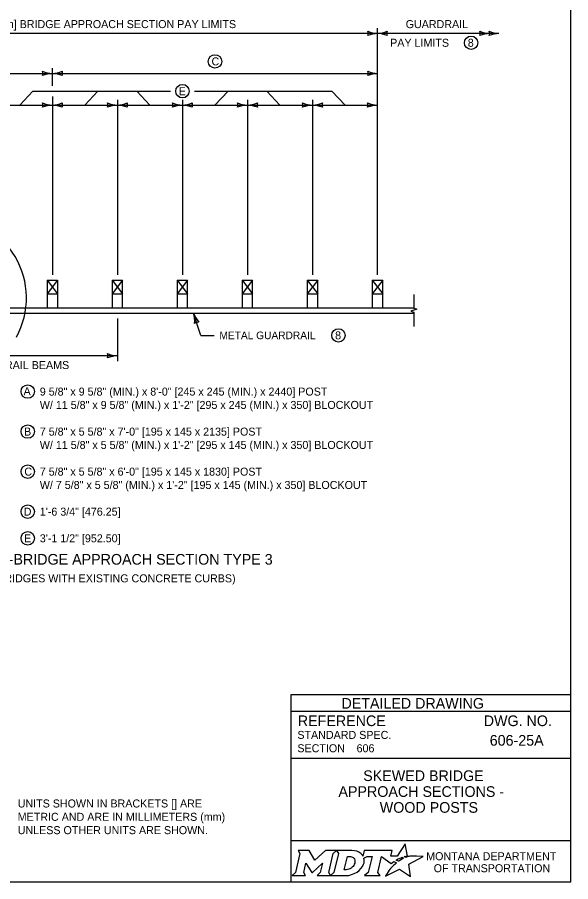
# Model space of a CAD drawing. Extents: x 49991.4 to 50021, y 49987.6 to 50011.4.
# Drawn here: x 50004.46 to 50008.61, y 50000.06 to 50006.54 of the extents above; entities that cross this region are included whole.
import ezdxf

# ---------------------------------------------------------------- set-up
doc = ezdxf.new("R2010")
doc.units = 0
for name, color, linetype in [('Level 1', 7, 'Continuous'), ('Level 2', 7, 'Continuous'), ('Level 3', 7, 'Continuous'), ('Level 4', 7, 'Continuous'), ('Level 6', 7, 'Continuous')]:
    doc.layers.add(name, color=color, linetype=linetype)

msp = doc.modelspace()

# ---------------------------------------------------------------- linework, layer by layer
at = {"layer": 'Level 1'}
for p, q in [((50004.6885, 50004.5728), (50004.7665, 50004.5728)), ((50004.7665, 50004.5728), (50004.6885, 50004.4688)), ((50004.6885, 50004.5728), (50004.7665, 50004.4688)), ((50004.6885, 50004.5728), (50004.6885, 50004.3647)), ((50004.7665, 50004.5728), (50004.7665, 50004.3647)), ((50005.1762, 50004.5728), (50005.2542, 50004.5728)), ((50005.2542, 50004.5728), (50005.1762, 50004.4688)), ((50005.1762, 50004.5728), (50005.2542, 50004.4688)), ((50005.1762, 50004.5728), (50005.1762, 50004.3647)), ((50005.2542, 50004.3647), (50005.2542, 50004.5728)), ((50005.6639, 50004.5728), (50005.7419, 50004.5728)), ((50005.7419, 50004.5728), (50005.6639, 50004.4688)), ((50005.6639, 50004.5728), (50005.7419, 50004.4688)), ((50005.6639, 50004.5728), (50005.6639, 50004.3647)), ((50005.7419, 50004.3647), (50005.7419, 50004.5728)), ((50006.1515, 50004.5728), (50006.2296, 50004.5728)), ((50006.2296, 50004.5728), (50006.1515, 50004.4688)), ((50006.1515, 50004.5728), (50006.2296, 50004.4688)), ((50006.1515, 50004.5728), (50006.1515, 50004.3647)), ((50006.2296, 50004.3647), (50006.2296, 50004.5728)), ((50006.6392, 50004.5728), (50006.7173, 50004.5728)), ((50006.7173, 50004.5728), (50006.6392, 50004.4688)), ((50006.6392, 50004.5728), (50006.7173, 50004.4688)), ((50006.6392, 50004.5728), (50006.6392, 50004.3647)), ((50006.7173, 50004.3647), (50006.7173, 50004.5728)), ((50007.1269, 50004.5728), (50007.205, 50004.5728)), ((50007.205, 50004.5728), (50007.1269, 50004.4688)), ((50007.1269, 50004.5728), (50007.205, 50004.4688)), ((50007.1269, 50004.5728), (50007.1269, 50004.3647)), ((50007.205, 50004.3647), (50007.205, 50004.5728)), ((50004.6885, 50004.4688), (50004.7665, 50004.4688)), ((50005.1762, 50004.4688), (50005.2542, 50004.4688)), ((50005.6639, 50004.4688), (50005.7419, 50004.4688)), ((50006.1515, 50004.4688), (50006.2296, 50004.4688)), ((50006.6392, 50004.4688), (50006.7173, 50004.4688)), ((50007.1269, 50004.4688), (50007.205, 50004.4688)), ((50001.87, 50004.3647), (50007.4379, 50004.3647)), ((50001.87, 50004.3256), (50007.4379, 50004.3256))]:
    msp.add_line(p, q, dxfattribs=at)
msp.add_lwpolyline([(50008.6146, 50011.2628), (50000.3356, 50011.2628), (50000.3356, 50000.0624), (50008.6146, 50000.0624)], close=True, dxfattribs=at)
at = {"layer": 'Level 2'}
for p, q in [((50008.6146, 50001.4624), (50006.5146, 50001.4624)), ((50006.5146, 50001.4624), (50006.5146, 50000.0624)), ((50008.6146, 50001.3374), (50006.5146, 50001.3374)), ((50007.0089, 50001.0629), (50007.0089, 50001.0629)), ((50008.2507, 50001.1223), (50008.2507, 50001.1223)), ((50008.6146, 50000.9874), (50006.5146, 50000.9874)), ((50007.5646, 50000.7383), (50007.5646, 50000.7383)), ((50008.6146, 50000.3693), (50006.5146, 50000.3693))]:
    msp.add_line(p, q, dxfattribs=at)
for points in [[(50006.5701, 50000.2974), (50006.5842, 50000.274), (50006.5507, 50000.1307), (50006.525, 50000.1082), (50006.6266, 50000.1082), (50006.6131, 50000.131), (50006.6293, 50000.2011), (50006.673, 50000.1321), (50006.6783, 50000.1321), (50006.7534, 50000.2016), (50006.737, 50000.1305), (50006.7123, 50000.1085), (50006.8139, 50000.1085), (50006.8001, 50000.1318), (50006.8333, 50000.2742)], [(50006.8333, 50000.2742), (50006.8586, 50000.2974), (50006.7762, 50000.2974), (50006.6966, 50000.2244), (50006.6521, 50000.2971), (50006.5701, 50000.2974)], [(50006.9722, 50000.2974), (50006.8586, 50000.2974), (50006.8733, 50000.2745), (50006.8394, 50000.1307), (50006.8139, 50000.1085), (50006.9245, 50000.1085)], [(50007.3771, 50000.2447), (50007.3668, 50000.2503), (50007.3784, 50000.2531), (50007.39, 50000.2551), (50007.3726, 50000.3452), (50007.3131, 50000.2539), (50007.2658, 50000.2532), (50007.2761, 50000.2973), (50007.0669, 50000.2974), (50007.0568, 50000.2549), (50007.051, 50000.2632)], [(50006.9962, 50000.2107), (50006.995, 50000.2026), (50006.9918, 50000.1933), (50006.9876, 50000.1851), (50006.982, 50000.1776), (50006.9755, 50000.1707), (50006.9676, 50000.1644), (50006.9593, 50000.1597), (50006.9502, 50000.1558), (50006.9411, 50000.1535), (50006.9319, 50000.1526), (50006.916, 50000.1526), (50006.9396, 50000.2526), (50006.9556, 50000.2526), (50006.9632, 50000.252), (50006.9708, 50000.2501), (50006.9774, 50000.2471), (50006.9835, 50000.2429), (50006.9883, 50000.2379), (50006.992, 50000.2319), (50006.9947, 50000.2257), (50006.9963, 50000.2183), (50006.9963, 50000.2153), (50006.9962, 50000.2107)], [(50007.0636, 50000.2383), (50007.0882, 50000.2514), (50007.1251, 50000.2514), (50007.0965, 50000.1309), (50007.069, 50000.1082), (50007.1852, 50000.1082), (50007.1682, 50000.1311), (50007.1964, 50000.2513), (50007.2677, 50000.1996), (50007.2888, 50000.2147), (50007.3085, 50000.2038)], [(50007.2527, 50000.1479), (50007.2374, 50000.1235), (50007.2327, 50000.116), (50007.2269, 50000.1074), (50007.2246, 50000.1031), (50007.3299, 50000.1562), (50007.4138, 50000.1011), (50007.4007, 50000.1938), (50007.5076, 50000.2522), (50007.4583, 50000.253), (50007.4282, 50000.2534), (50007.4074, 50000.2537), (50007.4006, 50000.2522), (50007.3957, 50000.251), (50007.3873, 50000.2487), (50007.3771, 50000.2447)], [(50007.3267, 50000.2171), (50007.3243, 50000.2154), (50007.306, 50000.225), (50007.3163, 50000.2307), (50007.3204, 50000.2329), (50007.329, 50000.2369), (50007.3347, 50000.2395), (50007.3426, 50000.2425), (50007.3499, 50000.2452), (50007.3617, 50000.2378), (50007.3577, 50000.2357), (50007.3531, 50000.2332), (50007.3489, 50000.231), (50007.3439, 50000.2281), (50007.342, 50000.227), (50007.3393, 50000.2254), (50007.3368, 50000.224), (50007.3345, 50000.2224), (50007.3319, 50000.2206), (50007.3292, 50000.2188), (50007.3267, 50000.2171)], [(50007.2666, 50000.164), (50007.2666, 50000.164)], [(50006.9702, 50000.1158), (50006.9786, 50000.1184), (50006.9916, 50000.1238), (50007.012, 50000.1348)]]:
    msp.add_lwpolyline(points, dxfattribs=at)
for centre, radius in [((50007.8676, 50006.3522), 0.05), ((50005.9468, 50006.2126), 0.0504), ((50005.7029, 50005.9893), 0.0504), ((50006.8729, 50004.1585), 0.05), ((50004.543, 50003.737), 0.0504), ((50004.543, 50003.437), 0.0504), ((50004.543, 50003.137), 0.0504), ((50004.543, 50002.837), 0.0504), ((50004.543, 50002.637), 0.0504)]:
    msp.add_circle(centre, radius, dxfattribs=at)
for centre, radius, start, end in [((50006.9953, 50000.219), 0.0709, 339.53292, 15.85821), ((50006.9513, 50000.2363), 0.1183, 300.91025, 339.13831)]:
    msp.add_arc(centre, radius, start, end, dxfattribs=at)
for centre, major_axis, ratio, start_param, end_param in [((50006.9701, 50000.25), (0.0834, -0.0037), 0.568097, 0.61298, 1.570796), ((50007.0257, 50000.2573), (0.0361, -0.0295), 0.469099, 1.225588, 1.570796), ((50007.2597, 50000.1559), (-0.00694, -0.00806), 0.008222, 0, 3.137361), ((50007.2764, 50000.1742), (-0.0098, -0.0102), 0.016458, 3.141593, 6.279097), ((50007.2974, 50000.1941), (-0.0112, -0.0097), 0.021651, 3.157348, 6.283185), ((50006.9248, 50000.2568), (0, 0.1484), 0.987302, 3.139398, 3.456847)]:
    msp.add_ellipse(centre, major_axis=major_axis, ratio=ratio, start_param=start_param, end_param=end_param, dxfattribs=at)
at = {"layer": 'Level 3'}
for p, q in [((50007.1658, 50004.6128), (50007.1658, 50006.4622)), ((50007.1658, 50006.4222), (50003.2643, 50006.4222)), ((50008.0755, 50006.4222), (50007.1658, 50006.4222)), ((50003.7521, 50006.1222), (50004.7275, 50006.1222)), ((50004.7275, 50006.0294), (50004.7275, 50006.1622)), ((50004.7275, 50006.1222), (50007.1658, 50006.1222)), ((50004.5818, 50005.9894), (50004.4836, 50005.8849)), ((50004.5818, 50005.9894), (50005.6125, 50005.9894)), ((50005.0696, 50005.9894), (50004.9713, 50005.8849)), ((50005.3607, 50005.9894), (50005.459, 50005.8849)), ((50005.7933, 50005.9894), (50006.8238, 50005.9894)), ((50006.0449, 50005.9894), (50005.9467, 50005.8849)), ((50006.3361, 50005.9894), (50006.4344, 50005.8849)), ((50006.8238, 50005.9894), (50006.9221, 50005.8849)), ((50004.7275, 50005.9494), (50004.7275, 50004.6128)), ((50005.2152, 50005.9249), (50005.2152, 50004.6128)), ((50005.7029, 50005.9249), (50005.7029, 50004.6128)), ((50006.1906, 50005.9249), (50006.1906, 50004.6128)), ((50006.6783, 50005.9249), (50006.6783, 50004.6128)), ((50004.2398, 50005.8849), (50004.7275, 50005.8849)), ((50004.7275, 50005.8849), (50005.2152, 50005.8849)), ((50005.2152, 50005.8849), (50005.7029, 50005.8849)), ((50005.7029, 50005.8849), (50006.1906, 50005.8849)), ((50006.1906, 50005.8849), (50006.6783, 50005.8849)), ((50006.6783, 50005.8849), (50007.1658, 50005.8849)), ((50005.8409, 50004.1586), (50005.7866, 50004.3256)), ((50005.2152, 50004.2856), (50005.2152, 50003.966)), ((50005.8409, 50004.1586), (50005.9407, 50004.1586)), ((50005.2152, 50004.006), (50003.2644, 50004.006))]:
    msp.add_line(p, q, dxfattribs=at)
for centre, radius, start, end in [((50007.1745, 50006.6332), 0.2113, 247.45601, 267.63952), ((50007.044, 50006.4222), 0.0521, 342.13882, 17.86118), ((50007.1549, 50006.6433), 0.2214, 272.82731, 292.07716), ((50007.2877, 50006.4222), 0.0521, 162.13882, 197.86118), ((50008.0144, 50006.6332), 0.2113, 247.45601, 267.63952), ((50007.8839, 50006.4222), 0.0521, 342.13882, 17.86118), ((50008.0842, 50006.6332), 0.2113, 247.45601, 267.63952), ((50007.9537, 50006.4222), 0.0521, 342.13882, 17.86118), ((50007.1768, 50006.201), 0.2214, 92.82731, 112.07716), ((50007.1571, 50006.2111), 0.2113, 67.45601, 87.63952), ((50008.0167, 50006.201), 0.2214, 92.82731, 112.07716), ((50008.0865, 50006.201), 0.2214, 92.82731, 112.07716), ((50004.7365, 50006.3389), 0.2168, 247.45601, 267.63952), ((50004.6025, 50006.1222), 0.0534, 342.13882, 17.86118), ((50004.7387, 50005.8952), 0.2273, 92.82731, 112.07716), ((50004.7163, 50006.3492), 0.2273, 272.82731, 292.07716), ((50004.7186, 50005.9055), 0.2168, 67.45601, 87.63952), ((50004.8526, 50006.1222), 0.0534, 162.13882, 197.86118), ((50007.1745, 50006.3333), 0.2113, 247.45601, 267.63952), ((50007.044, 50006.1222), 0.0521, 342.13882, 17.86118), ((50007.1768, 50005.901), 0.2214, 92.82731, 112.07716), ((50004.7364, 50006.1015), 0.2168, 247.45601, 267.63952), ((50004.6025, 50005.8849), 0.0534, 342.13882, 17.86118), ((50004.7387, 50005.6579), 0.2273, 92.82731, 112.07716), ((50004.7163, 50006.1118), 0.2273, 272.82731, 292.07716), ((50004.7186, 50005.6682), 0.2168, 67.45601, 87.63952), ((50004.8526, 50005.8849), 0.0534, 162.13882, 197.86118), ((50005.2241, 50006.1015), 0.2168, 247.45601, 267.63952), ((50005.0901, 50005.8849), 0.0534, 342.13882, 17.86118), ((50005.2264, 50005.6579), 0.2273, 92.82731, 112.07716), ((50005.204, 50006.1118), 0.2273, 272.82731, 292.07716), ((50005.2063, 50005.6682), 0.2168, 67.45601, 87.63952), ((50005.3403, 50005.8849), 0.0534, 162.13882, 197.86118), ((50005.7118, 50006.1015), 0.2168, 247.45601, 267.63952), ((50005.5778, 50005.8849), 0.0534, 342.13882, 17.86118), ((50005.7141, 50005.6579), 0.2273, 92.82731, 112.07716), ((50005.6917, 50006.1118), 0.2273, 272.82731, 292.07716), ((50005.694, 50005.6682), 0.2168, 67.45601, 87.63952), ((50005.8279, 50005.8849), 0.0534, 162.13882, 197.86118), ((50006.1995, 50006.1015), 0.2168, 247.45601, 267.63952), ((50006.0655, 50005.8849), 0.0534, 342.13882, 17.86118), ((50006.2018, 50005.6579), 0.2273, 92.82731, 112.07716), ((50006.1794, 50006.1118), 0.2273, 272.82731, 292.07716), ((50006.1816, 50005.6682), 0.2168, 67.45601, 87.63952), ((50006.3156, 50005.8849), 0.0534, 162.13882, 197.86118), ((50006.6872, 50006.1015), 0.2168, 247.45601, 267.63952), ((50006.5532, 50005.8849), 0.0534, 342.13882, 17.86118), ((50006.6895, 50005.6579), 0.2273, 92.82731, 112.07716), ((50006.667, 50006.1118), 0.2273, 272.82731, 292.07716), ((50006.6693, 50005.6682), 0.2168, 67.45601, 87.63952), ((50006.8033, 50005.8849), 0.0534, 162.13882, 197.86118), ((50007.1748, 50006.1015), 0.2168, 247.45601, 267.63952), ((50007.0408, 50005.8849), 0.0534, 342.13882, 17.86118), ((50007.177, 50005.6579), 0.2273, 92.82731, 112.07716), ((50005.5725, 50004.2655), 0.2223, 355.47877, 15.66228), ((50006.0043, 50004.4085), 0.233, 200.85007, 220.09992), ((50005.8263, 50004.2036), 0.0548, 90.16158, 125.88394), ((50005.2242, 50004.2227), 0.2168, 247.45601, 267.63952), ((50005.0902, 50004.006), 0.0534, 342.13882, 17.86118), ((50005.2264, 50003.779), 0.2273, 92.82731, 112.07716)]:
    msp.add_arc(centre, radius, start, end, dxfattribs=at)
at = {"layer": 'Level 4'}
msp.add_ellipse((50003.9225, 50004.439), major_axis=(0.6107, 0), ratio=0.996303, start_param=5.780694, end_param=7.853982, dxfattribs=at)
at = {"layer": 'Level 6'}
for p, q in [((50007.4379, 50004.4647), (50007.4379, 50004.3625)), ((50007.4596, 50004.3548), (50007.4163, 50004.3394)), ((50007.4163, 50004.3394), (50007.4379, 50004.3317)), ((50007.4379, 50004.3625), (50007.4596, 50004.3548)), ((50007.4379, 50004.3317), (50007.4379, 50004.2256))]:
    msp.add_line(p, q, dxfattribs=at)

# ---------------------------------------------------------------- texts
at = {"layer": 'Level 2'}
for s, height, p in [('25\'-0" [7.62 m] BRIDGE APPROACH SECTION PAY LIMITS', 0.06, (50003.9437, 50006.4622)), ('GUARDRAIL', 0.06, (50007.377, 50006.4622)), ('PAY LIMITS', 0.06, (50007.2607, 50006.3222)), ('8', 0.06, (50007.8426, 50006.3222)), ('C', 0.06, (50005.9212, 50006.1826)), ('E', 0.06, (50005.6749, 50005.9593)), ('METAL GUARDRAIL', 0.057017, (50005.9807, 50004.13)), ('8', 0.06, (50006.8479, 50004.1285)), ('USE DOUBLED GUARDRAIL BEAMS', 0.06, (50003.485, 50003.906)), ('A', 0.06, (50004.5116, 50003.7098)), ('9 5/8" x 9 5/8" (MIN.) x 8\'-0" [245 x 245 (MIN.) x 2440] POST', 0.06, (50004.6334, 50003.707)), ('W/ 11 5/8" x 9 5/8" (MIN.) x 1\'-2" [295 x 245 (MIN.) x 350] BLOCKOUT', 0.06, (50004.6334, 50003.607)), ('B', 0.06, (50004.5153, 50003.407)), ('7 5/8" x 5 5/8" x 7\'-0" [195 x 145 x 2135] POST', 0.06, (50004.6334, 50003.407)), ('W/ 11 5/8" x 5 5/8" (MIN.) x 1\'-2" [295 x 145 (MIN.) x 350] BLOCKOUT', 0.06, (50004.6334, 50003.307)), ('C', 0.06, (50004.5175, 50003.107)), ('7 5/8" x 5 5/8" x 6\'-0" [195 x 145 x 1830] POST', 0.06, (50004.6334, 50003.107)), ('W/ 7 5/8" x 5 5/8" (MIN.) x 1\'-2" [195 x 145 (MIN.) x 350] BLOCKOUT', 0.06, (50004.6334, 50003.007)), ('D', 0.06, (50004.5127, 50002.807)), ('1\'-6 3/4" [476.25]', 0.06, (50004.6334, 50002.807)), ('E', 0.06, (50004.5151, 50002.607)), ('3\'-1 1/2" [952.50]', 0.06, (50004.6334, 50002.607)), ('METAL GUARDRAIL-BRIDGE APPROACH SECTION TYPE 3', 0.08, (50003.3896, 50002.4395)), ('(FOR SKEWED BRIDGES WITH EXISTING CONCRETE CURBS)', 0.06, (50003.7254, 50002.3069)), ('DETAILED DRAWING', 0.0799, (50006.8956, 50001.3599)), ('REFERENCE', 0.08, (50006.5682, 50001.229)), ('DWG. NO.', 0.08, (50007.9624, 50001.229)), ('STANDARD SPEC.', 0.06, (50006.5649, 50001.133)), ('606-25A', 0.08, (50008.0073, 50001.0823)), ('SECTION', 0.06, (50006.5649, 50001.033)), ('606', 0.06, (50007.0089, 50001.0329)), ('SKEWED BRIDGE ', 0.08, (50007.0586, 50000.8173)), ('APPROACH SECTIONS - ', 0.08, (50006.8728, 50000.6983)), ('UNITS SHOWN IN BRACKETS [] ARE ', 0.06, (50004.4677, 50000.6189)), ('WOOD POSTS', 0.08, (50007.1826, 50000.5793)), ('METRIC AND ARE IN MILLIMETERS (mm) ', 0.06, (50004.4677, 50000.5189)), ('UNLESS OTHER UNITS ARE SHOWN.', 0.06, (50004.4677, 50000.4189)), ('MONTANA DEPARTMENT', 0.06, (50007.5308, 50000.2236)), ('OF TRANSPORTATION', 0.06, (50007.587, 50000.1336))]:
    msp.add_text(s, height=height, dxfattribs=at).set_placement(p)

doc.saveas('drawing.dxf')
